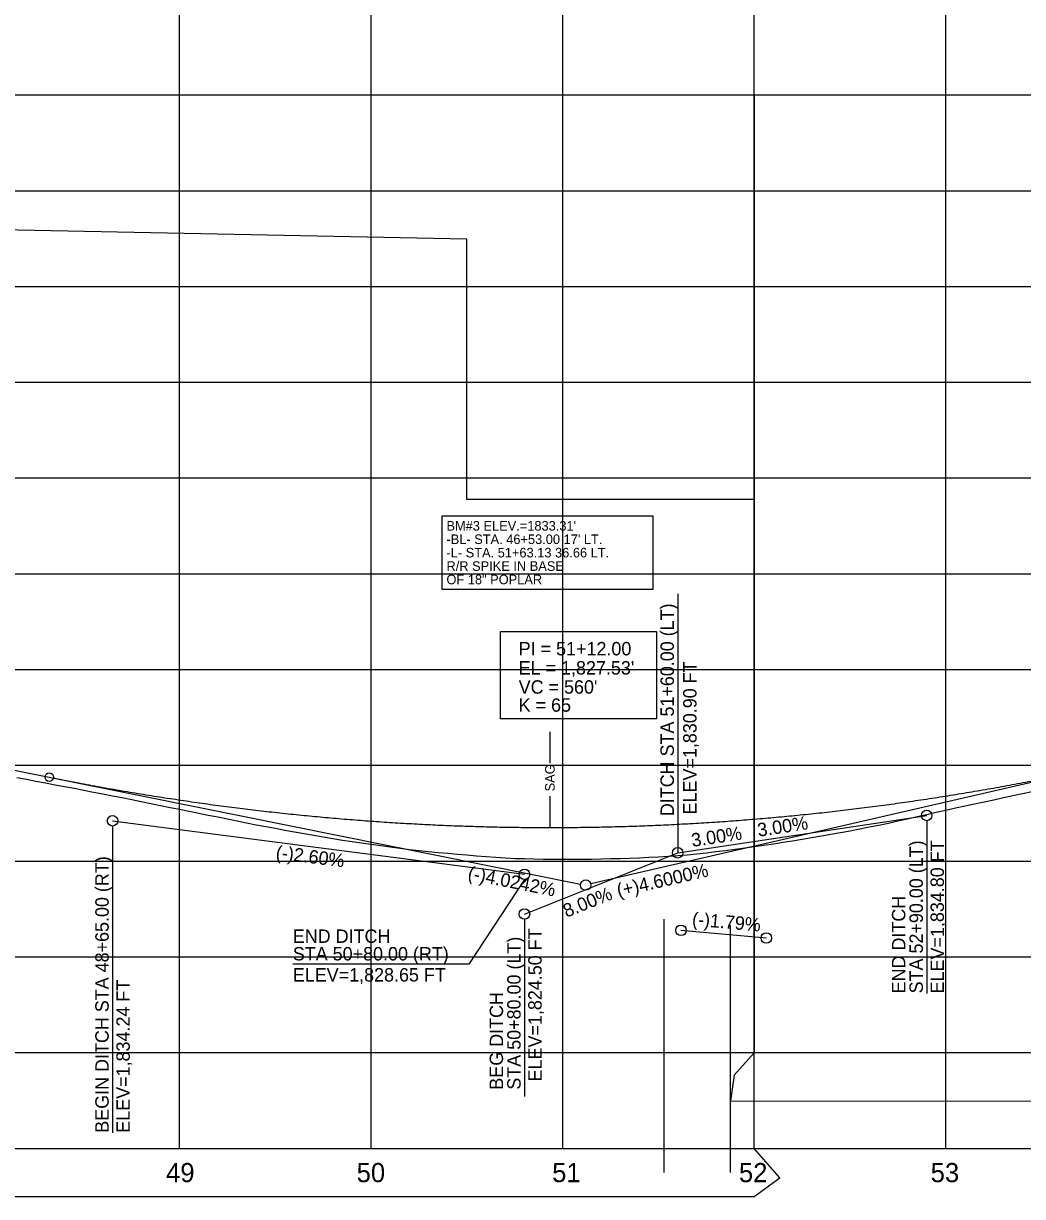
# Model space of a CAD drawing. Extents: x 553912 to 567693, y 512355 to 537539.
# Drawn here: x 561068 to 561589, y 513580 to 514193 of the extents above; entities that cross this region are included whole.
import ezdxf

# ---------------------------------------------------------------- set-up
doc = ezdxf.new("R2010")
doc.units = 0
for name, color, linetype in [('Default', 7, 'Continuous'), ('Exist DTM Spot Elevation Text', 7, 'Continuous'), ('Exist Profile Cell', 7, 'Continuous'), ('Exist Vertical Profile Ground Line', 7, 'Continuous'), ('Exist Vertical Profile Horizontal Axis Label Major', 7, 'Continuous'), ('Prop Vertical Profile Curve Label', 7, 'Continuous'), ('Prop Vertical Profile Ditch Grade Left', 7, 'Continuous'), ('Prop Vertical Profile Ditch Grade Left Label', 7, 'Continuous'), ('Prop Vertical Profile Ditch Grade Right', 7, 'Continuous'), ('Prop Vertical Profile Ditch Grade Right Label', 7, 'Continuous'), ('Prop Vertical Profile Grade', 7, 'Continuous'), ('Prop Vertical Profile Grade Label', 7, 'Continuous'), ('Prop VPI Ditch Grade Left Label', 7, 'Continuous'), ('Prop VPI Label', 7, 'Continuous'), ('Scratch_Level_3', 7, 'Continuous'), ('Scratch_Level_5', 7, 'Continuous'), ('Sheet Profile Grid Major CELL', 7, 'Continuous')]:
    doc.layers.add(name, color=color, linetype=linetype)

msp = doc.modelspace()

# ---------------------------------------------------------------- linework, layer by layer
at = {"layer": 'Default'}
for p, q in [((561342.75, 513823.08), (561342.75, 513806.72)), ((561342.75, 513789.44), (561342.75, 513773.08))]:
    msp.add_line(p, q, dxfattribs=at)
at = {"layer": 'Exist DTM Spot Elevation Text'}
msp.add_lwpolyline([(561286.26, 513897.59), (561396.7, 513897.59), (561396.7, 513935.59), (561286.26, 513935.59)], close=True, dxfattribs=at)
at = {"layer": 'Exist Profile Cell'}
msp.add_line((557249.45, 513605.4), (563849.45, 513605.4), dxfattribs=at)
msp.add_line((557249.45, 513605.4), (563849.45, 513605.4), dxfattribs=at)
at = {"layer": 'Exist Vertical Profile Ground Line'}
for points in [[(561064.45, 513799.19), (561069.45, 513798.25), (561074.45, 513797.3), (561079.45, 513796.35), (561084.45, 513795.43), (561089.45, 513794.52), (561094.45, 513793.54), (561099.45, 513792.57), (561104.45, 513791.59), (561109.45, 513790.62), (561114.45, 513789.66), (561119.45, 513788.67), (561124.45, 513787.66), (561129.45, 513786.65), (561134.45, 513785.63), (561139.45, 513784.62), (561144.45, 513783.61), (561149.45, 513782.61), (561154.45, 513781.59), (561159.45, 513780.58), (561164.45, 513779.58), (561169.45, 513778.57), (561174.45, 513777.57), (561179.45, 513776.56), (561184.45, 513775.56), (561189.45, 513774.55), (561194.45, 513773.57), (561199.45, 513772.67), (561204.45, 513771.77), (561209.45, 513770.87), (561214.45, 513769.97), (561219.45, 513769.07), (561224.45, 513768.17), (561229.45, 513767.27), (561234.45, 513766.52), (561239.45, 513765.81), (561244.45, 513765.1), (561249.45, 513764.38)], [(561064.45, 513799.19), (561069.45, 513798.25), (561074.45, 513797.3), (561079.45, 513796.35), (561084.45, 513795.43), (561089.45, 513794.52), (561094.45, 513793.54), (561099.45, 513792.57), (561104.45, 513791.59), (561109.45, 513790.62), (561114.45, 513789.66), (561119.45, 513788.67), (561124.45, 513787.66), (561129.45, 513786.65), (561134.45, 513785.63), (561139.45, 513784.62), (561144.45, 513783.61), (561149.45, 513782.61), (561154.45, 513781.59), (561159.45, 513780.58), (561164.45, 513779.58), (561169.45, 513778.57), (561174.45, 513777.57), (561179.45, 513776.56), (561184.45, 513775.56), (561189.45, 513774.55), (561194.45, 513773.57), (561199.45, 513772.67), (561204.45, 513771.77), (561209.45, 513770.87), (561214.45, 513769.97), (561219.45, 513769.07), (561224.45, 513768.17), (561229.45, 513767.27), (561234.45, 513766.52), (561239.45, 513765.81), (561244.45, 513765.1), (561249.45, 513764.38)], [(561249.45, 513764.38), (561254.45, 513763.67), (561259.45, 513762.96), (561264.45, 513762.24), (561269.45, 513761.52), (561274.45, 513761.03), (561279.45, 513760.58), (561284.45, 513760.12), (561289.45, 513759.66), (561294.45, 513759.19), (561299.45, 513758.73), (561304.45, 513758.27), (561309.45, 513757.89), (561314.45, 513757.58), (561319.45, 513757.27), (561324.45, 513756.96), (561329.45, 513756.82), (561334.45, 513756.71), (561339.45, 513756.6), (561344.45, 513756.52), (561349.45, 513756.53), (561354.45, 513756.54), (561359.45, 513756.55), (561364.45, 513756.61), (561369.45, 513756.73), (561374.45, 513756.85), (561379.45, 513756.94), (561384.45, 513757.13), (561389.45, 513757.33), (561394.45, 513757.55), (561399.45, 513757.85), (561404.45, 513758.19), (561409.45, 513758.53), (561414.45, 513758.9), (561419.45, 513759.41), (561424.45, 513759.93), (561429.45, 513760.47), (561434.45, 513761.08), (561439.45, 513761.75), (561444.45, 513762.42), (561449.45, 513763.08), (561454.45, 513763.85), (561459.45, 513764.62), (561464.45, 513765.4), (561469.45, 513766.13), (561474.45, 513766.97), (561479.45, 513767.83), (561484.45, 513768.68), (561489.45, 513769.56), (561494.45, 513770.49), (561499.45, 513771.42), (561504.45, 513772.37), (561509.45, 513773.37), (561514.45, 513774.38), (561519.45, 513775.38), (561524.45, 513776.51), (561529.45, 513777.64), (561534.45, 513778.76), (561539.45, 513779.89), (561544.45, 513781.02), (561549.45, 513782.16), (561554.45, 513783.28), (561559.45, 513784.37), (561564.45, 513785.4), (561569.45, 513786.43), (561574.45, 513787.55), (561579.45, 513788.68), (561584.45, 513789.75), (561589.45, 513790.82), (561594.45, 513791.95)], [(561249.45, 513764.38), (561254.45, 513763.67), (561259.45, 513762.96), (561264.45, 513762.24), (561269.45, 513761.52), (561274.45, 513761.03), (561279.45, 513760.58), (561284.45, 513760.12), (561289.45, 513759.66), (561294.45, 513759.19), (561299.45, 513758.73), (561304.45, 513758.27), (561309.45, 513757.89), (561314.45, 513757.58), (561319.45, 513757.27), (561324.45, 513756.96), (561329.45, 513756.82), (561334.45, 513756.71), (561339.45, 513756.6), (561344.45, 513756.52), (561349.45, 513756.53), (561354.45, 513756.54), (561359.45, 513756.55), (561364.45, 513756.61), (561369.45, 513756.73), (561374.45, 513756.85), (561379.45, 513756.94), (561384.45, 513757.13), (561389.45, 513757.33), (561394.45, 513757.55), (561399.45, 513757.85), (561404.45, 513758.19), (561409.45, 513758.53), (561414.45, 513758.9), (561419.45, 513759.41), (561424.45, 513759.93), (561429.45, 513760.47), (561434.45, 513761.08), (561439.45, 513761.75), (561444.45, 513762.42), (561449.45, 513763.08), (561454.45, 513763.85), (561459.45, 513764.62), (561464.45, 513765.4), (561469.45, 513766.13), (561474.45, 513766.97), (561479.45, 513767.83), (561484.45, 513768.68), (561489.45, 513769.56), (561494.45, 513770.49), (561499.45, 513771.42), (561504.45, 513772.37), (561509.45, 513773.37), (561514.45, 513774.38), (561519.45, 513775.38), (561524.45, 513776.51), (561529.45, 513777.64), (561534.45, 513778.76), (561539.45, 513779.89), (561544.45, 513781.02), (561549.45, 513782.16), (561554.45, 513783.28), (561559.45, 513784.37), (561564.45, 513785.4), (561569.45, 513786.43), (561574.45, 513787.55), (561579.45, 513788.68), (561584.45, 513789.75), (561589.45, 513790.82), (561594.45, 513791.95)]]:
    msp.add_lwpolyline(points, dxfattribs=at)
at = {"layer": 'Prop Vertical Profile Curve Label'}
msp.add_circle((561081.45, 513799.37), 2.25, dxfattribs=at)
at = {"layer": 'Prop Vertical Profile Ditch Grade Left'}
msp.add_lwpolyline([(561329.45, 513727.9), (561409.45, 513759.9), (561539.45, 513779.4)], dxfattribs=at)
at = {"layer": 'Prop Vertical Profile Ditch Grade Right'}
msp.add_line((561114.45, 513776.6), (561329.45, 513748.65), dxfattribs=at)
at = {"layer": 'Prop Vertical Profile Ditch Grade Right Label'}
msp.add_line((561114.45, 513773.85), (561114.45, 513613.72), dxfattribs=at)
msp.add_lwpolyline([(561329.45, 513745.9), (561300.45, 513701.67), (561208.55, 513701.67)], dxfattribs=at)
for centre in [(561114.45, 513776.6), (561329.45, 513748.65)]:
    msp.add_circle(centre, 2.75, dxfattribs=at)
at = {"layer": 'Prop Vertical Profile Grade'}
msp.add_line((561054.45, 513804.8), (561081.45, 513799.37), dxfattribs=at)
msp.add_spline([(561081.45, 513799.37), (561092.65, 513797.16), (561103.85, 513795.06), (561115.05, 513793.04), (561126.25, 513791.13), (561137.45, 513789.31), (561148.65, 513787.59), (561159.85, 513785.96), (561171.05, 513784.43), (561182.25, 513783), (561193.45, 513781.66), (561204.65, 513780.42), (561215.85, 513779.28), (561227.05, 513778.24), (561238.25, 513777.29), (561249.45, 513776.43), (561260.65, 513775.68), (561271.85, 513775.02), (561283.05, 513774.45), (561294.25, 513773.99), (561305.45, 513773.62), (561316.65, 513773.34), (561327.85, 513773.17), (561339.05, 513773.09), (561350.25, 513773.1), (561361.45, 513773.22), (561372.65, 513773.43), (561383.85, 513773.73), (561395.05, 513774.13), (561406.25, 513774.63), (561417.45, 513775.23), (561428.65, 513775.92), (561439.85, 513776.71), (561451.05, 513777.6), (561462.25, 513778.58), (561473.45, 513779.66), (561484.65, 513780.83), (561495.85, 513782.11), (561507.05, 513783.47), (561518.25, 513784.94), (561529.45, 513786.5), (561540.65, 513788.16), (561551.85, 513789.91), (561563.05, 513791.77), (561574.25, 513793.71), (561585.45, 513795.76), (561596.65, 513797.9), (561607.85, 513800.14), (561619.05, 513802.47), (561630.25, 513804.9), (561641.45, 513807.43)], degree=3, dxfattribs=at)
at = {"layer": 'Prop VPI Ditch Grade Left Label'}
for p, q in [((561539.45, 513776.65), (561539.45, 513686.48)), ((561329.45, 513725.15), (561329.45, 513632.6))]:
    msp.add_line(p, q, dxfattribs=at)
msp.add_lwpolyline([(561409.45, 513895.09), (561409.45, 513759.9)], dxfattribs=at)
for centre in [(561539.45, 513779.4), (561409.45, 513759.9), (561329.45, 513727.9)]:
    msp.add_circle(centre, 2.75, dxfattribs=at)
at = {"layer": 'Prop VPI Label'}
for p, q in [((561641.45, 513807.43), (561364.13, 513743.65)), ((561081.45, 513799.37), (561358.76, 513743.57))]:
    msp.add_line(p, q, dxfattribs=at)
msp.add_lwpolyline([(561316.88, 513875.39), (561398.4, 513875.39), (561398.4, 513829.84), (561316.88, 513829.84)], close=True, dxfattribs=at)
msp.add_circle((561361.45, 513743.03), 2.75, dxfattribs=at)
at = {"layer": 'Scratch_Level_3'}
for p, q in [((561402.34, 513592.9), (561402.34, 513725.15)), ((561411.16, 513719.4), (561455.73, 513715.4)), ((561437.04, 513592.9), (561437.04, 513722.04))]:
    msp.add_line(p, q, dxfattribs=at)
for centre in [(561411.16, 513719.4), (561455.73, 513715.4)]:
    msp.add_circle(centre, 2.75, dxfattribs=at)
at = {"layer": 'Scratch_Level_5'}
for points in [[(561449.45, 514155.4), (561449.45, 513655.4), (561439, 513643.83), (561436.95, 513630.4), (562847.93, 513630.25), (562899.45, 513630.4), (562849.45, 513655.4), (562849.45, 514155.4)], [(561299.4, 514080.35), (560049.45, 514105.4), (560049.45, 513605.4), (560036.61, 513588.79), (560049.45, 513580.4), (561449.45, 513580.4), (561462.72, 513590.13), (561449.45, 513605.4), (561449.45, 513944.35), (561299.4, 513944.35)]]:
    msp.add_lwpolyline(points, close=True, dxfattribs=at)
at = {"layer": 'Sheet Profile Grid Major CELL'}
for p, q in [((561149.45, 513605.4), (561149.45, 514805.4)), ((561249.45, 513605.4), (561249.45, 514805.4)), ((561349.45, 513605.4), (561349.45, 514805.4)), ((561449.45, 513605.4), (561449.45, 514805.4)), ((561549.45, 513605.4), (561549.45, 514805.4)), ((563849.45, 514155.4), (557249.45, 514155.4)), ((563849.45, 514105.4), (557249.45, 514105.4)), ((563849.45, 514055.4), (557249.45, 514055.4)), ((563849.45, 514005.4), (557249.45, 514005.4)), ((563849.45, 513955.4), (557249.45, 513955.4)), ((563849.45, 513905.4), (557249.45, 513905.4)), ((563849.45, 513855.4), (557249.45, 513855.4)), ((563849.45, 513805.4), (557249.45, 513805.4)), ((563849.45, 513755.4), (557249.45, 513755.4)), ((563849.45, 513705.4), (557249.45, 513705.4)), ((563849.45, 513655.4), (557249.45, 513655.4))]:
    msp.add_line(p, q, dxfattribs=at)

# ---------------------------------------------------------------- texts
at = {"layer": 'Default'}
msp.add_text('SAG', height=5, rotation=90, dxfattribs=at).set_placement((561345.25, 513791.94))
at = {"layer": 'Exist DTM Spot Elevation Text'}
for s, p in [("BM#3 ELEV.=1833.31'", (561288.76, 513928.09)), ("-BL- STA. 46+53.00 17' LT.", (561288.76, 513921.09)), ('-L- STA. 51+63.13 36.66 LT.', (561288.76, 513914.09)), ('R/R SPIKE IN BASE', (561288.76, 513907.09)), ('OF 18" POPLAR', (561288.76, 513900.09))]:
    msp.add_text(s, height=5, dxfattribs=at).set_placement(p)
at = {"layer": 'Exist Vertical Profile Horizontal Axis Label Major'}
for s, p in [('49', (561142.39, 513587.9)), ('49', (561142.39, 513587.9)), ('50', (561241.88, 513587.9)), ('50', (561241.88, 513587.9)), ('51', (561343.94, 513587.9)), ('51', (561343.94, 513587.9)), ('52', (561441.44, 513587.9)), ('52', (561441.44, 513587.9)), ('53', (561541.52, 513587.9)), ('53', (561541.52, 513587.9))]:
    msp.add_text(s, height=10, dxfattribs=at).set_placement(p)
at = {"layer": 'Prop Vertical Profile Curve Label'}
for s, p in [("VC = 560'", (561326.45, 513842.96)), ('K = 65', (561326.45, 513833.54))]:
    msp.add_text(s, height=7, dxfattribs=at).set_placement(p)
at = {"layer": 'Prop Vertical Profile Ditch Grade Left Label'}
for s, rotation, p in [('3.00%', 8.53077, (561451.61, 513768.26)), ('3.00%', 8.53077, (561417.13, 513762.91)), ('8.00%', 21.80141, (561351.38, 513725.97))]:
    msp.add_text(s, height=7, rotation=rotation, dxfattribs=at).set_placement(p)
at = {"layer": 'Prop Vertical Profile Ditch Grade Right'}
msp.add_text('(-)2.60%', height=7, rotation=352.59309, dxfattribs=at).set_placement((561199.41, 513756.84))
at = {"layer": 'Prop Vertical Profile Ditch Grade Right Label'}
for s, p in [('BEGIN DITCH STA 48+65.00 (RT)', (561112.45, 513613.72)), ('ELEV=1,834.24 FT', (561123.45, 513613.72))]:
    msp.add_text(s, height=7, rotation=90, dxfattribs=at).set_placement(p)
for s, p in [('END DITCH', (561208.55, 513712.85)), ('STA 50+80.00 (RT)', (561208.55, 513703.67)), ('ELEV=1,828.65 FT', (561208.55, 513692.67))]:
    msp.add_text(s, height=7, dxfattribs=at).set_placement(p)
at = {"layer": 'Prop Vertical Profile Grade Label'}
for s, rotation, p in [('(-)4.0242%', 348.62352, (561299.52, 513746.09)), ('(+)4.6000%', 12.95276, (561378.56, 513736.71))]:
    msp.add_text(s, height=7, rotation=rotation, dxfattribs=at).set_placement(p)
at = {"layer": 'Prop VPI Ditch Grade Left Label'}
for s, p in [('DITCH STA 51+60.00 (LT)', (561407.47, 513779.01)), ('ELEV=1,830.90 FT', (561419.31, 513779.92)), ('STA 52+90.00 (LT)', (561537.45, 513686.48)), ('ELEV=1,834.80 FT', (561548.45, 513686.48)), ('END DITCH', (561528.28, 513686.48)), ('ELEV=1,824.50 FT', (561338.45, 513640.52)), ('STA 50+80.00 (LT)', (561327.48, 513636.2)), ('BEG DITCH', (561318.31, 513636.2))]:
    msp.add_text(s, height=7, rotation=90, dxfattribs=at).set_placement(p)
at = {"layer": 'Prop VPI Label'}
for s, p in [('PI = 51+12.00', (561326.45, 513862.96)), ("EL = 1,827.53'", (561326.45, 513852.96))]:
    msp.add_text(s, height=7, dxfattribs=at).set_placement(p)
at = {"layer": 'Scratch_Level_3'}
msp.add_text('(-)1.79%', height=7, rotation=354.87165, dxfattribs=at).set_placement((561416.75, 513721.93))

doc.saveas('drawing.dxf')
